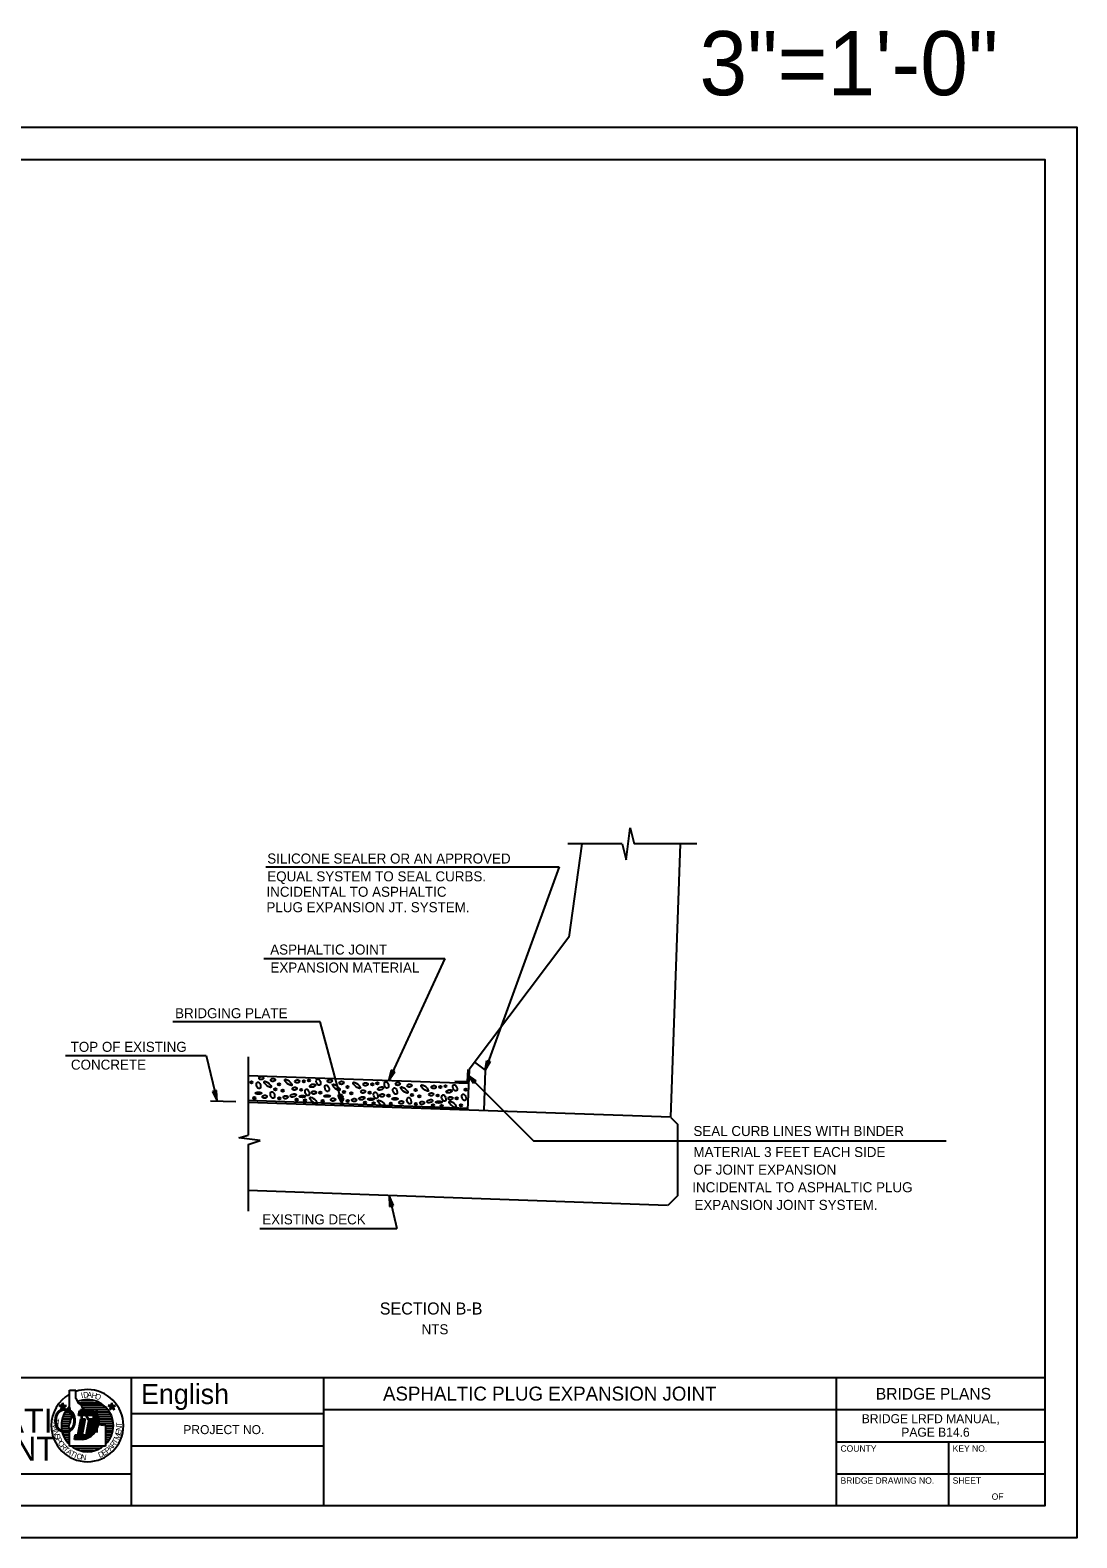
# Model space of a CAD drawing. Extents: x 0 to 11.3, y 0 to 7.8.
# Drawn here: x 5.89 to 11.33, y 0 to 7.84 of the extents above; entities that cross this region are included whole.
import ezdxf

# ---------------------------------------------------------------- set-up
doc = ezdxf.new("R2010")
doc.units = 0
for name, color, linetype in [('BORDER_ANNO_Cutsheet', 7, 'Continuous'), ('BRDG_ANNO_Anno-Sheet', 7, 'Continuous'), ('BRDG_ANNO_General-Notes', 7, 'Continuous'), ('BRDG_BASE_Obj-Line', 7, 'Continuous')]:
    doc.layers.add(name, color=color, linetype=linetype)

msp = doc.modelspace()

# ---------------------------------------------------------------- linework, layer by layer
at = {"layer": 'BORDER_ANNO_Cutsheet'}
msp.add_lwpolyline([(0, 7.3333), (11.3333, 7.3333), (11.3333, 0), (0, 0)], close=True, dxfattribs=at)
at = {"layer": 'BRDG_ANNO_Anno-Sheet'}
for p, q in [((0.5, 0.8333), (6.4167, 0.8333)), ((6.4167, 0.1667), (6.4167, 0.8333)), ((6.4167, 0.8333), (11.1667, 0.8333)), ((7.4167, 0.1667), (7.4167, 0.8333)), ((10.0833, 0.1667), (10.0833, 0.8333)), ((6.0948, 0.6808), (6.0948, 0.7677)), ((6.0948, 0.7677), (6.1277, 0.7677)), ((6.1277, 0.7244), (6.1277, 0.7677)), ((6.1277, 0.7244), (6.1365, 0.7087)), ((6.1365, 0.7087), (6.1381, 0.7017)), ((6.155, 0.7148), (6.2194, 0.7148)), ((6.0671, 0.68), (6.0408, 0.6885)), ((6.0552, 0.6885), (6.0408, 0.6885)), ((6.0525, 0.68), (6.0408, 0.6885)), ((6.0644, 0.6885), (6.0479, 0.666)), ((6.0525, 0.68), (6.0479, 0.666)), ((6.0598, 0.6746), (6.0479, 0.666)), ((6.0525, 0.68), (6.079, 0.6885)), ((6.0552, 0.6885), (6.0598, 0.7023)), ((6.0552, 0.6885), (6.0717, 0.666)), ((6.0598, 0.6746), (6.0598, 0.7023)), ((6.0644, 0.6885), (6.0598, 0.7023)), ((6.0598, 0.6746), (6.0717, 0.666)), ((6.0604, 0.6308), (6.1063, 0.6308)), ((6.0644, 0.6885), (6.079, 0.6885)), ((6.0656, 0.6427), (6.0994, 0.6427)), ((6.0671, 0.68), (6.079, 0.6885)), ((6.0671, 0.68), (6.0717, 0.666)), ((6.0723, 0.6548), (6.0975, 0.6548)), ((6.0806, 0.6669), (6.0979, 0.6669)), ((6.0915, 0.6787), (6.0954, 0.6787)), ((6.0981, 0.6687), (6.0948, 0.6808)), ((6.0981, 0.6583), (6.0981, 0.6687)), ((6.0981, 0.6496), (6.0981, 0.6583)), ((6.1, 0.6427), (6.0981, 0.6496)), ((6.1069, 0.6392), (6.1, 0.6427)), ((6.1069, 0.6304), (6.1069, 0.6392)), ((6.1069, 0.6252), (6.1069, 0.6304)), ((6.1381, 0.7017), (6.1554, 0.6896)), ((6.139, 0.7027), (6.2502, 0.7027)), ((6.1417, 0.6356), (6.1469, 0.6619)), ((6.2204, 0.6356), (6.1417, 0.6356)), ((6.1465, 0.6356), (6.1513, 0.6619)), ((6.1469, 0.6619), (6.2042, 0.6619)), ((6.1517, 0.6356), (6.1567, 0.6619)), ((6.155, 0.6908), (6.269, 0.6908)), ((6.1554, 0.6896), (6.1608, 0.6756)), ((6.1571, 0.6356), (6.1619, 0.6619)), ((6.1596, 0.6787), (6.2835, 0.6787)), ((6.1608, 0.6756), (6.1781, 0.6619)), ((6.1623, 0.6356), (6.1673, 0.6619)), ((6.1675, 0.6356), (6.1725, 0.6619)), ((6.1719, 0.6669), (6.2942, 0.6669)), ((6.1729, 0.6356), (6.1777, 0.6619)), ((6.1781, 0.6356), (6.1831, 0.6619)), ((6.1835, 0.6356), (6.1883, 0.6619)), ((6.1887, 0.6356), (6.1937, 0.6619)), ((6.1942, 0.6356), (6.199, 0.6619)), ((6.1994, 0.6356), (6.2044, 0.6619)), ((6.1998, 0.5248), (6.224, 0.654)), ((6.2046, 0.6356), (6.2094, 0.6604)), ((6.2058, 0.5285), (6.2287, 0.6506)), ((6.21, 0.6356), (6.2144, 0.659)), ((6.2121, 0.5335), (6.2331, 0.6462)), ((6.2152, 0.6356), (6.2192, 0.6567)), ((6.2173, 0.6183), (6.2204, 0.6356)), ((6.2185, 0.5396), (6.2375, 0.6415)), ((6.2229, 0.6548), (6.3025, 0.6548)), ((6.2252, 0.5467), (6.2417, 0.6354)), ((6.2323, 0.5563), (6.2456, 0.6273)), ((6.2367, 0.6427), (6.3092, 0.6427)), ((6.2442, 0.6308), (6.3144, 0.6308)), ((6.3225, 0.68), (6.296, 0.6885)), ((6.3079, 0.68), (6.296, 0.6885)), ((6.3106, 0.6885), (6.296, 0.6885)), ((6.3198, 0.6885), (6.3033, 0.666)), ((6.3079, 0.68), (6.3033, 0.666)), ((6.3152, 0.6746), (6.3033, 0.666)), ((6.3079, 0.68), (6.3342, 0.6885)), ((6.3106, 0.6885), (6.3152, 0.7023)), ((6.3106, 0.6885), (6.3271, 0.666)), ((6.3152, 0.6746), (6.3152, 0.7023)), ((6.3198, 0.6885), (6.3152, 0.7023)), ((6.3152, 0.6746), (6.3271, 0.666)), ((6.3198, 0.6885), (6.3342, 0.6885)), ((6.3225, 0.68), (6.3342, 0.6885)), ((6.3225, 0.68), (6.3271, 0.666)), ((6.4167, 0.6458), (7.4167, 0.6458)), ((7.4167, 0.6667), (10.0833, 0.6667)), ((10.0833, 0.6667), (11.1667, 0.6667)), ((6.0521, 0.5827), (6.0925, 0.5827)), ((6.0525, 0.5948), (6.0969, 0.5948)), ((6.0527, 0.5708), (6.0938, 0.5708)), ((6.0542, 0.6069), (6.0994, 0.6069)), ((6.0544, 0.5587), (6.0994, 0.5587)), ((6.0569, 0.6188), (6.1037, 0.6188)), ((6.0896, 0.575), (6.0929, 0.5835)), ((6.0948, 0.5698), (6.0896, 0.575)), ((6.0929, 0.5835), (6.0948, 0.5906)), ((6.0948, 0.5906), (6.1, 0.601)), ((6.0981, 0.5646), (6.0948, 0.5698)), ((6.0948, 0.5506), (6.1, 0.5558)), ((6.0948, 0.4758), (6.0948, 0.5506)), ((6.1, 0.561), (6.0981, 0.5646)), ((6.1, 0.6096), (6.1033, 0.6167)), ((6.1, 0.601), (6.1, 0.6096)), ((6.1, 0.5558), (6.1, 0.561)), ((6.1033, 0.6167), (6.1069, 0.6252)), ((6.1381, 0.535), (6.1537, 0.6183)), ((6.1387, 0.5106), (6.159, 0.6183)), ((6.1442, 0.5106), (6.1644, 0.6183)), ((6.1494, 0.5106), (6.1696, 0.6183)), ((6.1537, 0.6183), (6.1767, 0.6183)), ((6.1548, 0.5106), (6.175, 0.6183)), ((6.1767, 0.6183), (6.161, 0.535)), ((6.1812, 0.535), (6.1969, 0.6183)), ((6.1823, 0.5158), (6.2015, 0.6183)), ((6.1879, 0.5183), (6.2067, 0.6183)), ((6.1937, 0.521), (6.2121, 0.6183)), ((6.1969, 0.6183), (6.2173, 0.6183)), ((6.2406, 0.5725), (6.2485, 0.615)), ((6.2469, 0.5925), (6.2494, 0.5887)), ((6.2475, 0.5948), (6.3225, 0.5948)), ((6.2481, 0.6188), (6.3181, 0.6188)), ((6.2492, 0.6069), (6.3208, 0.6069)), ((6.2494, 0.5887), (6.2598, 0.5871)), ((6.2598, 0.5871), (6.2702, 0.5854)), ((6.2702, 0.5854), (6.2754, 0.5923)), ((6.2754, 0.5923), (6.2823, 0.5819)), ((6.2817, 0.5827), (6.3229, 0.5827)), ((6.2823, 0.5819), (6.2823, 0.4758)), ((6.2823, 0.5587), (6.3206, 0.5587)), ((6.2825, 0.5708), (6.3223, 0.5708)), ((6.0571, 0.5469), (6.0946, 0.5469)), ((6.0612, 0.5348), (6.0942, 0.5348)), ((6.0665, 0.5227), (6.0942, 0.5227)), ((6.0733, 0.5108), (6.0944, 0.5108)), ((6.0819, 0.4987), (6.0942, 0.4987)), ((6.0925, 0.4869), (6.0946, 0.4869)), ((6.2823, 0.4758), (6.0948, 0.4758)), ((6.1198, 0.5106), (6.1244, 0.535)), ((6.1642, 0.5106), (6.1198, 0.5106)), ((6.1229, 0.5106), (6.1275, 0.535)), ((6.1244, 0.535), (6.1381, 0.535)), ((6.1283, 0.5106), (6.1329, 0.535)), ((6.1335, 0.5106), (6.1381, 0.535)), ((6.16, 0.5106), (6.1646, 0.535)), ((6.161, 0.535), (6.1812, 0.535)), ((6.1654, 0.5108), (6.17, 0.535)), ((6.171, 0.5123), (6.1752, 0.535)), ((6.1767, 0.514), (6.1804, 0.535)), ((6.2823, 0.5469), (6.3179, 0.5469)), ((6.2823, 0.5348), (6.3137, 0.5348)), ((6.2823, 0.5227), (6.3083, 0.5227)), ((6.2823, 0.5108), (6.3017, 0.5108)), ((6.2823, 0.4987), (6.2933, 0.4987)), ((6.4167, 0.4792), (7.4167, 0.4792)), ((10.0833, 0.5), (11.1667, 0.5)), ((10.6667, 0.1667), (10.6667, 0.5)), ((6.2502, 0.4637), (6.124, 0.4637)), ((6.2196, 0.4519), (6.1558, 0.4519)), ((4.6667, 0.3333), (6.4167, 0.3333)), ((10.0833, 0.3333), (11.1667, 0.3333))]:
    msp.add_line(p, q, dxfattribs=at)
msp.add_lwpolyline([(0.5, 7.1667), (11.1667, 7.1667), (11.1667, 0.1667), (0.5, 0.1667)], close=True, dxfattribs=at)
for centre, radius, start, end in [((6.1875, 0.5833), 0.1875, 119.63312, 180), ((6.1875, 0.5833), 0.1875, 90, 108.596), ((6.1875, 0.5833), 0.1354, 90, 112.14518), ((6.1875, 0.5833), 0.1875, 0, 90), ((6.1875, 0.5833), 0.1354, 0, 90), ((6.1875, 0.5833), 0.1354, 133.19257, 180), ((6.1944, 0.608), 0.0547, 343.49805, 79.73615), ((6.1875, 0.5833), 0.1875, 180, 270), ((6.1875, 0.5833), 0.1354, 180.26444, 226.79463), ((6.145, 0.6127), 0.1039, 280.64795, 348.77185), ((6.1875, 0.5833), 0.1875, 270, 0), ((6.1875, 0.5833), 0.1354, 314.427, 0), ((6.1875, 0.5833), 0.1354, 232.5658, 270), ((6.1875, 0.5833), 0.1354, 270, 307.45359)]:
    msp.add_arc(centre, radius, start, end, dxfattribs=at)
at = {"layer": 'BRDG_ANNO_General-Notes'}
for p, q in [((7.116, 3.4877), (8.641, 3.4877)), ((8.641, 3.4877), (8.2561, 2.4322)), ((7.1051, 3.0127), (8.0464, 3.0127)), ((8.0464, 3.0127), (7.7531, 2.3765)), ((7.3985, 2.683), (6.6326, 2.683)), ((7.513, 2.2559), (7.3985, 2.683)), ((6.0736, 2.5083), (6.8047, 2.5083)), ((6.8047, 2.5083), (6.8622, 2.2696)), ((7.767, 2.4314), (7.7531, 2.3765)), ((7.7858, 2.4227), (7.767, 2.4314)), ((8.2561, 2.4322), (8.2645, 2.4824)), ((8.2821, 2.4759), (8.2561, 2.4322)), ((8.2645, 2.4824), (8.2821, 2.4759)), ((7.7531, 2.3765), (7.7858, 2.4227)), ((8.1663, 2.4049), (8.5072, 2.064)), ((8.1951, 2.3629), (8.1663, 2.4049)), ((8.1663, 2.4049), (8.2083, 2.3761)), ((8.2083, 2.3761), (8.1951, 2.3629)), ((6.8594, 2.3262), (6.8389, 2.3213)), ((6.8389, 2.3213), (6.8622, 2.2696)), ((6.8622, 2.2696), (6.8594, 2.3262)), ((7.491, 2.3018), (7.5091, 2.3066)), ((7.513, 2.2559), (7.491, 2.3018)), ((7.5091, 2.3066), (7.513, 2.2559)), ((6.9601, 2.2661), (6.8285, 2.271)), ((8.5072, 2.064), (10.6534, 2.064)), ((7.7562, 1.7793), (7.7972, 1.6088)), ((7.7562, 1.7793), (7.7591, 1.7227)), ((7.7795, 1.7276), (7.7562, 1.7793)), ((7.7591, 1.7227), (7.7795, 1.7276)), ((7.0851, 1.6088), (7.7972, 1.6088))]:
    msp.add_line(p, q, dxfattribs=at)
at = {"layer": 'BRDG_BASE_Obj-Line'}
for p, q in [((8.9901, 3.5255), (9.0109, 3.6921)), ((9.0109, 3.6921), (9.0317, 3.6088)), ((8.9692, 3.6088), (8.6854, 3.6088)), ((8.759, 3.6088), (8.6905, 3.1225)), ((8.9692, 3.6088), (8.9901, 3.5255)), ((9.3562, 3.6088), (9.0317, 3.6088)), ((9.222, 2.1866), (9.272, 3.6088)), ((8.6905, 3.1225), (8.1724, 2.4352)), ((7.0233, 2.5002), (7.0233, 2.0942)), ((8.1724, 2.4352), (8.1649, 2.2237)), ((8.1651, 2.3701), (8.1674, 2.4353)), ((8.2013, 2.4735), (8.2561, 2.4322)), ((8.2561, 2.4322), (8.2487, 2.2208)), ((8.1698, 2.3619), (7.0233, 2.4022)), ((8.1651, 2.3701), (8.099, 2.3723)), ((8.1653, 2.2329), (7.0233, 2.2731)), ((9.222, 2.1865), (7.0233, 2.264)), ((9.222, 2.186), (9.2582, 2.1492)), ((9.2582, 1.7791), (9.2582, 2.1492)), ((6.9747, 2.0804), (7.0233, 2.0942)), ((7.0858, 2.0665), (6.9747, 2.0804)), ((7.0233, 2.0456), (7.0858, 2.0665)), ((7.0233, 2.0456), (7.0233, 1.6987)), ((9.2053, 1.7283), (7.0233, 1.805)), ((9.2582, 1.7791), (9.2054, 1.7283))]:
    msp.add_line(p, q, dxfattribs=at)
for centre in [(7.0409, 2.3682), (7.1841, 2.3582), (7.3133, 2.3732), (7.3397, 2.3778), (7.6695, 2.3583), (7.696, 2.3629), (8.0498, 2.3483), (7.0555, 2.2868), (7.1652, 2.3324), (7.1855, 2.2854), (7.2037, 2.3255), (7.2753, 2.2781), (7.2993, 2.3291), (7.3198, 2.2744), (7.3984, 2.3142), (7.4118, 2.2718), (7.5215, 2.3175), (7.5404, 2.3433), (7.5418, 2.2704), (7.56, 2.3106), (7.6556, 2.3142), (7.7522, 2.2996), (7.7546, 2.2992), (7.8753, 2.3029), (7.8942, 2.3287), (7.9138, 2.296), (8.0094, 2.2996), (8.0234, 2.3437), (8.1084, 2.2846), (8.1555, 2.3303), (7.6315, 2.2632), (7.676, 2.2595), (7.7656, 2.2572), (7.8956, 2.2559), (7.9854, 2.2486), (8.0299, 2.2449), (8.1302, 2.248)]:
    msp.add_circle(centre, 0.00592, dxfattribs=at)
for centre, major_axis, ratio in [((7.0774, 2.3522), (0.0053, -0.0164), 0.596558), ((7.0919, 2.39), (-0.0118, -0.001), 0.670054), ((7.1253, 2.3575), (-0.0181, 0.0153), 0.3337), ((7.1528, 2.3805), (-0.0118, -0.001), 0.670054), ((7.2322, 2.3677), (-0.0181, 0.0153), 0.3337), ((7.2784, 2.373), (-0.0118, -0.001), 0.670054), ((7.3589, 2.3507), (-0.0147, -0.0044), 0.494228), ((7.3892, 2.3692), (0.0053, -0.0164), 0.596558), ((7.4336, 2.3373), (0.0053, -0.0164), 0.596558), ((7.4481, 2.375), (-0.0118, -0.001), 0.670054), ((7.4816, 2.3425), (-0.0181, 0.0153), 0.3337), ((7.509, 2.3656), (-0.0118, -0.001), 0.670054), ((7.5884, 2.3528), (-0.0181, 0.0153), 0.3337), ((7.6347, 2.3581), (-0.0118, -0.001), 0.670054), ((7.7431, 2.3546), (0.0053, -0.0164), 0.596558), ((7.8019, 2.3604), (-0.0118, -0.001), 0.670054), ((7.8628, 2.351), (-0.0118, -0.001), 0.670054), ((7.9423, 2.3382), (-0.0181, 0.0153), 0.3337), ((7.9885, 2.3435), (-0.0118, -0.001), 0.670054), ((8.0993, 2.3396), (0.0053, -0.0164), 0.596558), ((7.0774, 2.3118), (-0.0166, -0.0001), 0.297909), ((7.1093, 2.2933), (-0.0118, -0.001), 0.670054), ((7.1504, 2.3023), (0.0053, -0.0164), 0.596558), ((7.2184, 2.2909), (-0.0118, -0.001), 0.670054), ((7.2583, 2.3), (-0.0147, -0.0044), 0.494228), ((7.2654, 2.3352), (-0.0118, -0.001), 0.670054), ((7.3054, 2.295), (-0.0166, -0.0001), 0.297909), ((7.3307, 2.3155), (0.0053, -0.0164), 0.596558), ((7.3631, 2.274), (-0.0181, 0.0153), 0.3337), ((7.3659, 2.315), (-0.0118, -0.001), 0.670054), ((7.4336, 2.2969), (-0.0166, -0.0001), 0.297909), ((7.4655, 2.2783), (-0.0118, -0.001), 0.670054), ((7.5066, 2.2874), (0.0053, -0.0164), 0.596558), ((7.5747, 2.2759), (-0.0118, -0.001), 0.670054), ((7.6146, 2.2851), (-0.0147, -0.0044), 0.494228), ((7.6217, 2.3202), (-0.0118, -0.001), 0.670054), ((7.6616, 2.2801), (-0.0166, -0.0001), 0.297909), ((7.6869, 2.3006), (0.0053, -0.0164), 0.596558), ((7.7169, 2.2594), (-0.0181, 0.0153), 0.3337), ((7.7127, 2.3361), (-0.0147, -0.0044), 0.494228), ((7.7197, 2.3004), (-0.0118, -0.001), 0.670054), ((7.7874, 2.2823), (-0.0166, -0.0001), 0.297909), ((7.7875, 2.3227), (0.0053, -0.0164), 0.596558), ((7.8354, 2.328), (-0.0181, 0.0153), 0.3337), ((7.8604, 2.2728), (0.0053, -0.0164), 0.596558), ((7.9684, 2.2705), (-0.0147, -0.0044), 0.494228), ((7.9755, 2.3056), (-0.0118, -0.001), 0.670054), ((8.0407, 2.286), (0.0053, -0.0164), 0.596558), ((8.0689, 2.3212), (-0.0147, -0.0044), 0.494228), ((8.076, 2.2854), (-0.0118, -0.001), 0.670054), ((8.1459, 2.2901), (0.0053, -0.0164), 0.596558), ((7.8193, 2.2637), (-0.0118, -0.001), 0.670054), ((7.9285, 2.2613), (-0.0118, -0.001), 0.670054), ((8.0155, 2.2655), (-0.0166, -0.0001), 0.297909), ((8.0879, 2.253), (-0.0181, 0.0153), 0.3337)]:
    msp.add_ellipse(centre, major_axis=major_axis, ratio=ratio, dxfattribs=at)

# ---------------------------------------------------------------- texts
at = {"layer": 'BRDG_ANNO_Anno-Sheet'}
for s, height, p in [('3"=1\'-0"', 0.33333, (9.3708, 7.5)), ('English', 0.10417, (6.4669, 0.6956)), ('ASPHALTIC PLUG EXPANSION JOINT', 0.072709, (7.725, 0.7135)), ('BRIDGE PLANS', 0.060625, (10.2878, 0.7188)), ('TRANSPORTATION', 0.125, (4.7156, 0.5469)), ('BRIDGE LRFD MANUAL,', 0.046875, (10.2148, 0.5961)), ('PROJECT NO.', 0.046875, (6.6864, 0.5392)), ('PAGE B14.6', 0.04688, (10.4204, 0.5258)), ('DEPARTMENT', 0.125, (4.8731, 0.401)), ('COUNTY', 0.03313, (10.1042, 0.4479)), ('KEY NO.', 0.03313, (10.6875, 0.4479)), ('BRIDGE DRAWING NO.', 0.033125, (10.1042, 0.2812)), ('SHEET', 0.03313, (10.6875, 0.2812)), ('OF', 0.03313, (10.8904, 0.1979))]:
    msp.add_text(s, height=height, dxfattribs=at).set_placement(p)
for s, rotation, p in [('I', 11.95188, (6.1573, 0.726)), ('D', 5.21184, (6.1671, 0.7281)), ('A', 357.8718, (6.1856, 0.7294)), ('H', 349.63177, (6.2073, 0.7279)), ('O', 342.19173, (6.2248, 0.7244)), ('R', 266.0275, (6.0088, 0.6025)), ('A', 273.76404, (6.0077, 0.5802)), ('T', 259.42648, (6.0127, 0.6252)), ('N', 280.37584, (6.0096, 0.5571)), ('E', 75.61046, (6.3598, 0.5323)), ('N', 83.19321, (6.365, 0.5544)), ('T', 90.49256, (6.3673, 0.5765)), ('S', 287.92792, (6.0144, 0.5346)), ('P', 295.49755, (6.0219, 0.5135)), ('O', 302.64464, (6.0319, 0.4933)), ('R', 309.90789, (6.0446, 0.4742)), ('T', 317.1211, (6.0592, 0.4571)), ('P', 37.66562, (6.291, 0.4365)), ('A', 45, (6.3085, 0.4502)), ('R', 52.33438, (6.3246, 0.4671)), ('T', 59.03624, (6.3379, 0.485)), ('M', 67.71394, (6.3502, 0.5069)), ('A', 324.63754, (6.076, 0.4419)), ('T', 331.75026, (6.0948, 0.429)), ('I', 337.0213, (6.1165, 0.4179)), ('O', 343.32869, (6.1275, 0.4135)), ('N', 351.65981, (6.1529, 0.4067)), ('D', 22.98872, (6.251, 0.4152)), ('E', 30.54757, (6.2719, 0.4246))]:
    msp.add_text(s, height=0.029, rotation=rotation, dxfattribs=at).set_placement(p)
at = {"layer": 'BRDG_ANNO_General-Notes'}
for s, height, p in [('SILICONE SEALER OR AN APPROVED', 0.052083, (7.1229, 3.5057)), ('EQUAL SYSTEM TO SEAL CURBS.', 0.052083, (7.1229, 3.413)), ('INCIDENTAL TO ASPHALTIC', 0.052083, (7.1187, 3.3328)), ('PLUG EXPANSION JT. SYSTEM.', 0.052083, (7.1187, 3.2526)), ('ASPHALTIC JOINT', 0.052083, (7.1384, 3.0325)), ('EXPANSION MATERIAL', 0.052083, (7.1396, 2.9391)), ('BRIDGING PLATE', 0.052083, (6.6436, 2.7016)), ('TOP OF EXISTING', 0.052083, (6.1005, 2.5267)), ('CONCRETE', 0.05208, (6.1018, 2.434)), ('SEAL CURB LINES WITH BINDER', 0.052083, (9.3392, 2.089)), ('MATERIAL 3 FEET EACH SIDE ', 0.052083, (9.3392, 1.98)), ('OF JOINT EXPANSION', 0.052083, (9.3392, 1.8883)), ('INCIDENTAL TO ASPHALTIC PLUG', 0.052083, (9.3333, 1.7967)), ('EXPANSION JOINT SYSTEM.', 0.052083, (9.3447, 1.705)), ('EXISTING DECK', 0.052083, (7.0969, 1.6296)), ('SECTION B-B', 0.0625, (7.7081, 1.1611)), ('NTS', 0.05208, (7.9256, 1.0583))]:
    msp.add_text(s, height=height, dxfattribs=at).set_placement(p)

doc.saveas('drawing.dxf')
